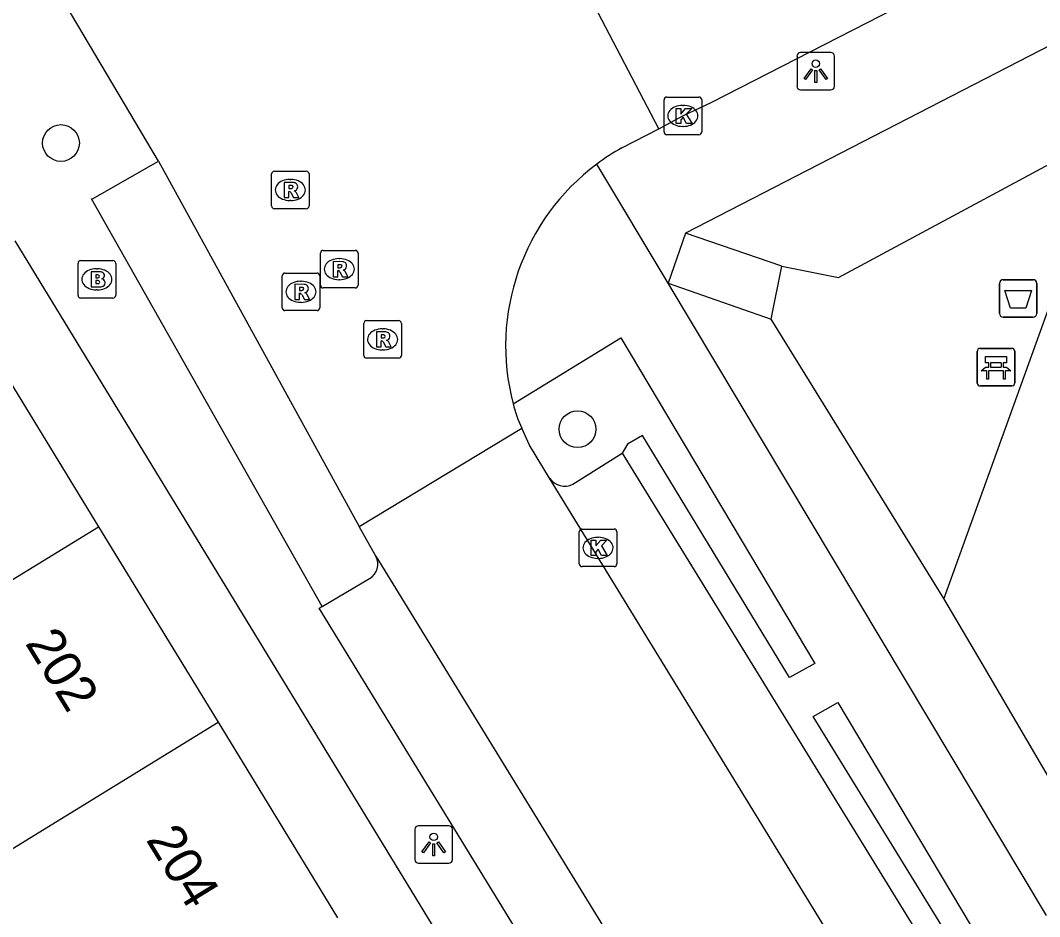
# Model space of a CAD drawing. Extents: x 159888 to 160757, y 384031 to 384746.
# Drawn here: x 160516.19 to 160543.3, y 384260.69 to 384284.54 of the extents above; entities that cross this region are included whole.
import ezdxf

# ---------------------------------------------------------------- set-up
doc = ezdxf.new("R2010")
doc.units = 0
for name, color, linetype in [('IMGEO_Afvalbak', 7, 'Continuous'), ('IMGEO_Bank', 7, 'Continuous'), ('IMGEO_Boom', 7, 'Continuous'), ('IMGEO_Brandkraan', 7, 'Continuous'), ('IMGEO_Groenvoorziening', 7, 'Continuous'), ('IMGEO_Kolk', 7, 'Continuous'), ('IMGEO_Lichtpunt', 7, 'Continuous'), ('IMGEO_Pand', 7, 'Continuous'), ('IMGEO_Pand_nummerreeks', 7, 'Continuous'), ('IMGEO_Parkeervlak_open', 7, 'Continuous'), ('IMGEO_Rijbaan_lokaal_open', 7, 'Continuous'), ('IMGEO_Rioolput', 7, 'Continuous'), ('IMGEO_Voetpad_open', 7, 'Continuous')]:
    doc.layers.add(name, color=color, linetype=linetype)

msp = doc.modelspace()

# ---------------------------------------------------------------- linework, layer by layer
at = {"layer": 'IMGEO_Afvalbak'}
for p, q in [((160542.23, 384276.738), (160542.23, 384277.538)), ((160542.23, 384277.538), (160542.23, 384276.738)), ((160542.33, 384277.638), (160543.12, 384277.638)), ((160543.12, 384277.638), (160542.33, 384277.638)), ((160543.22, 384277.538), (160543.22, 384276.738)), ((160543.22, 384276.738), (160543.22, 384277.538)), ((160543.12, 384276.638), (160542.33, 384276.638)), ((160542.33, 384276.638), (160543.12, 384276.638))]:
    msp.add_line(p, q, dxfattribs=at)
msp.add_lwpolyline([(160542.373, 384277.352), (160543.077, 384277.352), (160542.928, 384276.882), (160542.522, 384276.882), (160542.373, 384277.352)], dxfattribs=at)
for centre, start, end in [((160542.33, 384277.538), 90, 180), ((160542.33, 384277.538), 90, 180), ((160543.12, 384277.538), 0, 90), ((160543.12, 384277.538), 360, 90), ((160542.33, 384276.738), 180, 270), ((160542.33, 384276.738), 180, 270), ((160543.12, 384276.738), 270, 0), ((160543.12, 384276.738), 270, 0)]:
    msp.add_arc(centre, 0.1, start, end, dxfattribs=at)
at = {"layer": 'IMGEO_Bank'}
for p, q in [((160541.636, 384274.886), (160541.636, 384275.727)), ((160541.636, 384275.727), (160541.636, 384274.886)), ((160541.711, 384275.811), (160542.552, 384275.811)), ((160542.552, 384275.811), (160541.711, 384275.811)), ((160542.636, 384275.736), (160542.636, 384274.895)), ((160542.636, 384274.895), (160542.636, 384275.736)), ((160541.945, 384275.317), (160541.945, 384275.423)), ((160541.989, 384275.423), (160541.989, 384275.317)), ((160542.277, 384275.429), (160541.995, 384275.429)), ((160542.283, 384275.317), (160542.283, 384275.423)), ((160542.327, 384275.423), (160542.327, 384275.317)), ((160542.333, 384275.209), (160541.94, 384275.209)), ((160541.995, 384275.311), (160542.277, 384275.311)), ((160542.561, 384274.811), (160541.72, 384274.811)), ((160541.72, 384274.811), (160542.561, 384274.811))]:
    msp.add_line(p, q, dxfattribs=at)
for points in [[(160541.939, 384275.429), (160541.853, 384275.429), (160541.853, 384275.59), (160542.416, 384275.59), (160542.416, 384275.429), (160542.333, 384275.429)], [(160541.883, 384275.209), (160541.741, 384275.209), (160541.853, 384275.311), (160541.939, 384275.311)], [(160541.933, 384275.202), (160541.933, 384274.995), (160541.89, 384274.995), (160541.89, 384275.202)], [(160542.333, 384275.311), (160542.416, 384275.311), (160542.528, 384275.209), (160542.389, 384275.209)], [(160542.383, 384275.202), (160542.383, 384274.995), (160542.339, 384274.995), (160542.339, 384275.202)]]:
    msp.add_lwpolyline(points, dxfattribs=at)
for centre, radius, start, end in [((160541.714, 384275.733), 0.0779, 92.4484, 184.2845), ((160541.714, 384275.733), 0.0779, 92.4484, 184.2845), ((160542.558, 384275.733), 0.0779, 2.4484, 94.2845), ((160542.558, 384275.733), 0.0779, 2.4484, 94.2845), ((160541.938, 384275.422), 0.00671, 2.8957, 87.1043), ((160541.995, 384275.422), 0.00671, 92.8957, 177.1043), ((160542.277, 384275.422), 0.00671, 2.8957, 87.1043), ((160542.334, 384275.422), 0.00671, 92.8957, 177.1043), ((160541.883, 384275.202), 0.00671, 2.8957, 87.1043), ((160541.94, 384275.202), 0.00671, 92.8957, 177.1043), ((160541.938, 384275.318), 0.00671, 272.8957, 357.1043), ((160541.995, 384275.318), 0.00671, 182.8957, 267.1043), ((160542.277, 384275.318), 0.00671, 272.8957, 357.1043), ((160542.334, 384275.318), 0.00671, 182.8957, 267.1043), ((160542.332, 384275.202), 0.00671, 2.8957, 87.1043), ((160542.389, 384275.202), 0.00671, 92.8957, 177.1043), ((160541.714, 384274.889), 0.0779, 182.4484, 274.2845), ((160541.714, 384274.889), 0.0779, 182.4484, 274.2845), ((160542.558, 384274.889), 0.0779, 272.4484, 4.2845), ((160542.558, 384274.889), 0.0779, 272.4484, 4.2845)]:
    msp.add_arc(centre, radius, start, end, dxfattribs=at)
at = {"layer": 'IMGEO_Boom'}
for centre in [(160517.266, 384281.275), (160531.005, 384273.658)]:
    msp.add_circle(centre, 0.489, dxfattribs=at)
at = {"layer": 'IMGEO_Brandkraan'}
for p, q in [((160517.796, 384278.147), (160518.648, 384278.147)), ((160517.721, 384277.221), (160517.721, 384278.073)), ((160518.209, 384277.927), (160518.234, 384277.927)), ((160518.722, 384278.073), (160518.722, 384277.221)), ((160518.232, 384277.367), (160518.207, 384277.367)), ((160518.648, 384277.147), (160517.796, 384277.147))]:
    msp.add_line(p, q, dxfattribs=at)
for points in [[(160517.796, 384278.147), (160518.648, 384278.147)], [(160517.721, 384277.221), (160517.721, 384278.073)], [(160518.069, 384277.847), (160518.069, 384277.447), (160518.282, 384277.447)], [(160518.3, 384277.847), (160518.069, 384277.847)], [(160518.722, 384278.073), (160518.722, 384277.221)], [(160518.248, 384277.766), (160518.194, 384277.766), (160518.194, 384277.69)], [(160518.194, 384277.69), (160518.247, 384277.69)], [(160518.256, 384277.614), (160518.194, 384277.614), (160518.194, 384277.533)], [(160518.194, 384277.533), (160518.256, 384277.533)], [(160518.648, 384277.147), (160517.796, 384277.147)]]:
    msp.add_lwpolyline(points, dxfattribs=at)
for centre, radius, start, end in [((160517.798, 384278.071), 0.0765, 91.552, 178.448), ((160517.798, 384278.071), 0.0765, 91.552, 178.448), ((160518.646, 384278.071), 0.0765, 1.552, 88.448), ((160518.646, 384278.071), 0.0765, 1.552, 88.448), ((160518.304, 384277.702), 0.145, 59.4692, 91.5367), ((160518.329, 384277.749), 0.0922, 285.5137, 58.1501), ((160518.249, 384277.728), 0.0379, 267.8285, 90.9355), ((160518.257, 384277.573), 0.0404, 269.8759, 90.5077), ((160518.334, 384277.557), 0.105, 301.3115, 78.989), ((160518.288, 384277.698), 0.251, 268.6676, 293.5347), ((160517.798, 384277.223), 0.0765, 181.552, 268.448), ((160517.798, 384277.223), 0.0765, 181.552, 268.448), ((160518.646, 384277.223), 0.0765, 271.552, 358.448), ((160518.646, 384277.223), 0.0765, 271.552, 358.448)]:
    msp.add_arc(centre, radius, start, end, dxfattribs=at)
for centre, major_axis, ratio, start_param, end_param in [((160518.208, 384277.647), (-0.387, 0.002), 0.722429, 4.712389, 7.853982), ((160518.233, 384277.647), (-0.39, 0.002), 0.717154, 1.570796, 4.712389)]:
    msp.add_ellipse(centre, major_axis=major_axis, ratio=ratio, start_param=start_param, end_param=end_param, dxfattribs=at)
at = {"layer": 'IMGEO_Groenvoorziening'}
for points in [[(160536.442, 384278.002), (160537.944, 384277.697), (160549.322, 384283.817), (160551.212, 384280.795), (160550.654, 384280.266), (160550.225, 384279.629), (160550.169, 384278.862), (160550.319, 384278.053), (160551.037, 384276.806)], [(160551.037, 384276.806), (160544.321, 384279.062), (160540.748, 384269.155)], [(160540.748, 384269.155), (160536.155, 384276.583)], [(160543.871, 384263.833), (160541.766, 384267.42), (160540.748, 384269.155)]]:
    msp.add_lwpolyline(points, dxfattribs=at)
at = {"layer": 'IMGEO_Kolk'}
for p, q in [((160533.307, 384281.571), (160533.307, 384282.423)), ((160533.382, 384282.497), (160534.234, 384282.497)), ((160534.308, 384282.423), (160534.308, 384281.571)), ((160533.795, 384282.277), (160533.82, 384282.277)), ((160533.818, 384281.717), (160533.793, 384281.717)), ((160534.234, 384281.497), (160533.382, 384281.497)), ((160531.05, 384270.076), (160531.05, 384270.928)), ((160531.125, 384271.002), (160531.977, 384271.002)), ((160531.538, 384270.782), (160531.563, 384270.782)), ((160532.051, 384270.928), (160532.051, 384270.076)), ((160531.561, 384270.222), (160531.536, 384270.222)), ((160531.977, 384270.002), (160531.125, 384270.002))]:
    msp.add_line(p, q, dxfattribs=at)
for points in [[(160533.307, 384281.571), (160533.307, 384282.423)], [(160533.382, 384282.497), (160534.234, 384282.497)], [(160534.308, 384282.423), (160534.308, 384281.571)], [(160533.628, 384282.197), (160533.751, 384282.197), (160533.751, 384282.046), (160533.881, 384282.197), (160534.045, 384282.197), (160533.899, 384282.046), (160534.052, 384281.797), (160533.9, 384281.797), (160533.815, 384281.961), (160533.751, 384281.894), (160533.751, 384281.797), (160533.628, 384281.797), (160533.628, 384282.197)], [(160534.234, 384281.497), (160533.382, 384281.497)], [(160531.05, 384270.076), (160531.05, 384270.928)], [(160531.125, 384271.002), (160531.977, 384271.002)], [(160532.051, 384270.928), (160532.051, 384270.076)], [(160531.371, 384270.702), (160531.494, 384270.702), (160531.494, 384270.551), (160531.624, 384270.702), (160531.788, 384270.702), (160531.642, 384270.551), (160531.795, 384270.302), (160531.643, 384270.302), (160531.558, 384270.466), (160531.494, 384270.399), (160531.494, 384270.302), (160531.371, 384270.302), (160531.371, 384270.702)], [(160531.977, 384270.002), (160531.125, 384270.002)]]:
    msp.add_lwpolyline(points, dxfattribs=at)
for centre, start, end in [((160533.384, 384282.421), 91.552, 178.448), ((160533.384, 384282.421), 91.552, 178.448), ((160534.232, 384282.421), 1.552, 88.448), ((160534.232, 384282.421), 1.552, 88.448), ((160533.384, 384281.573), 181.552, 268.448), ((160533.384, 384281.573), 181.552, 268.448), ((160534.232, 384281.573), 271.552, 358.448), ((160534.232, 384281.573), 271.552, 358.448), ((160531.127, 384270.926), 91.552, 178.448), ((160531.127, 384270.926), 91.552, 178.448), ((160531.975, 384270.926), 1.552, 88.448), ((160531.975, 384270.926), 1.552, 88.448), ((160531.127, 384270.078), 181.552, 268.448), ((160531.127, 384270.078), 181.552, 268.448), ((160531.975, 384270.078), 271.552, 358.448), ((160531.975, 384270.078), 271.552, 358.448)]:
    msp.add_arc(centre, 0.0765, start, end, dxfattribs=at)
for centre, major_axis, ratio, start_param, end_param in [((160533.794, 384281.997), (-0.387, 0.002), 0.722429, 4.712389, 7.853982), ((160533.819, 384281.997), (-0.39, 0.002), 0.717154, 1.570796, 4.712389), ((160531.537, 384270.502), (-0.387, 0.002), 0.722429, 4.712389, 7.853982), ((160531.562, 384270.502), (-0.39, 0.002), 0.717154, 1.570796, 4.712389)]:
    msp.add_ellipse(centre, major_axis=major_axis, ratio=ratio, start_param=start_param, end_param=end_param, dxfattribs=at)
at = {"layer": 'IMGEO_Lichtpunt'}
for p, q in [((160536.843, 384283.589), (160536.843, 384282.782)), ((160536.843, 384283.589), (160536.843, 384282.782)), ((160537.745, 384283.684), (160536.937, 384283.684)), ((160537.745, 384283.684), (160536.937, 384283.684)), ((160537.839, 384282.782), (160537.839, 384283.589)), ((160537.839, 384282.782), (160537.839, 384283.589)), ((160536.937, 384282.688), (160537.745, 384282.688)), ((160536.937, 384282.688), (160537.745, 384282.688)), ((160526.681, 384263.012), (160526.681, 384262.205)), ((160526.681, 384263.012), (160526.681, 384262.205)), ((160527.583, 384263.107), (160526.775, 384263.107)), ((160527.583, 384263.107), (160526.775, 384263.107)), ((160527.677, 384262.205), (160527.677, 384263.012)), ((160527.677, 384262.205), (160527.677, 384263.012)), ((160526.775, 384262.111), (160527.583, 384262.111)), ((160526.775, 384262.111), (160527.583, 384262.111))]:
    msp.add_line(p, q, dxfattribs=at)
for points in [[(160537.217, 384283.253), (160537.256, 384283.225), (160537.068, 384282.963), (160537.03, 384282.99), (160537.217, 384283.253)], [(160537.429, 384283.225), (160537.467, 384283.252), (160537.654, 384282.99), (160537.615, 384282.962), (160537.429, 384283.225)], [(160537.319, 384283.205), (160537.366, 384283.205), (160537.366, 384282.883), (160537.319, 384282.883), (160537.319, 384283.205)], [(160527.055, 384262.676), (160527.094, 384262.648), (160526.906, 384262.386), (160526.868, 384262.413), (160527.055, 384262.676)], [(160527.157, 384262.628), (160527.204, 384262.628), (160527.204, 384262.306), (160527.157, 384262.306), (160527.157, 384262.628)], [(160527.267, 384262.648), (160527.305, 384262.675), (160527.492, 384262.413), (160527.453, 384262.385), (160527.267, 384262.648)]]:
    msp.add_lwpolyline(points, dxfattribs=at)
for centre in [(160537.342, 384283.387), (160527.18, 384262.81)]:
    msp.add_circle(centre, 0.0994, dxfattribs=at)
for centre, start, end in [((160536.937, 384283.589), 90, 180), ((160536.937, 384283.589), 90, 180), ((160537.745, 384283.589), 0, 90), ((160537.745, 384283.589), 0, 90), ((160536.937, 384282.782), 180, 270), ((160536.937, 384282.782), 180, 270), ((160537.745, 384282.782), 270, 0), ((160537.745, 384282.782), 270, 360), ((160526.775, 384263.012), 90, 180), ((160526.775, 384263.012), 90, 180), ((160527.583, 384263.012), 0, 90), ((160527.583, 384263.012), 0, 90), ((160526.775, 384262.205), 180, 270), ((160526.775, 384262.205), 180, 270), ((160527.583, 384262.205), 270, 0), ((160527.583, 384262.205), 270, 360)]:
    msp.add_arc(centre, 0.0946, start, end, dxfattribs=at)
at = {"layer": 'IMGEO_Pand'}
for points in [[(160511.406, 384266.852), (160508.164, 384272.127), (160515.039, 384276.335), (160518.261, 384271.065)], [(160511.406, 384266.852), (160518.261, 384271.065)], [(160518.261, 384271.065), (160521.443, 384265.86)], [(160511.115, 384259.493), (160514.645, 384261.683), (160521.443, 384265.86)], [(160521.443, 384265.86), (160524.625, 384260.656)]]:
    msp.add_lwpolyline(points, dxfattribs=at)
at = {"layer": 'IMGEO_Parkeervlak_open'}
for points in [[(160530.88, 384272.193), (160532.196, 384273.02)], [(160524.213, 384268.938), (160525.476, 384269.683)]]:
    msp.add_lwpolyline(points, dxfattribs=at)
for centre, radius, start, end in [((160530.667, 384272.638), 0.494, 215.1581, 295.5926), ((160525.247, 384270.064), 0.445, 300.9358, 28.554)]:
    msp.add_arc(centre, radius, start, end, dxfattribs=at)
at = {"layer": 'IMGEO_Rijbaan_lokaal_open'}
for points in [[(160533.164, 384281.656), (160533.808, 384281.997), (160534.575, 384282.359), (160579.578, 384305.42)], [(160533.164, 384281.656), (160530.447, 384286.864)], [(160519.864, 384280.79), (160516.788, 384285.989)], [(160532.184, 384281.146), (160533.164, 384281.656)], [(160519.864, 384280.79), (160525.198, 384271.067)], [(160525.198, 384271.067), (160529.522, 384273.687)], [(160530.263, 384272.354), (160529.728, 384273.233), (160529.522, 384273.687)], [(160545.852, 384246.914), (160538, 384259.726), (160530.263, 384272.354)], [(160525.638, 384270.277), (160525.198, 384271.067)], [(160525.638, 384270.277), (160538.092, 384250)]]:
    msp.add_lwpolyline(points, dxfattribs=at)
for centre, radius, start, end in [((160535.135, 384275.867), 6.048, 119.2067, 126.7321), ((160535.129, 384275.877), 6.036, 126.747, 194.7842), ((160532.652, 384275.155), 3.457, 193.6867, 205.1288)]:
    msp.add_arc(centre, radius, start, end, dxfattribs=at)
at = {"layer": 'IMGEO_Rioolput'}
for p, q in [((160522.94, 384280.525), (160523.792, 384280.525)), ((160522.865, 384279.599), (160522.865, 384280.451)), ((160523.353, 384280.305), (160523.378, 384280.305)), ((160523.866, 384280.451), (160523.866, 384279.599)), ((160523.376, 384279.745), (160523.351, 384279.745)), ((160523.792, 384279.525), (160522.94, 384279.525)), ((160524.243, 384278.418), (160525.095, 384278.418)), ((160524.168, 384277.492), (160524.168, 384278.344)), ((160524.656, 384278.198), (160524.681, 384278.198)), ((160525.169, 384278.344), (160525.169, 384277.492)), ((160523.224, 384277.815), (160524.076, 384277.815)), ((160523.149, 384276.889), (160523.149, 384277.741)), ((160523.637, 384277.595), (160523.662, 384277.595)), ((160524.15, 384277.741), (160524.15, 384276.889)), ((160524.679, 384277.638), (160524.654, 384277.638)), ((160525.095, 384277.418), (160524.243, 384277.418)), ((160523.66, 384277.035), (160523.635, 384277.035)), ((160524.076, 384276.815), (160523.224, 384276.815)), ((160525.32, 384275.623), (160525.32, 384276.475)), ((160525.395, 384276.549), (160526.247, 384276.549)), ((160526.321, 384276.475), (160526.321, 384275.623)), ((160525.808, 384276.329), (160525.833, 384276.329)), ((160525.831, 384275.769), (160525.806, 384275.769)), ((160526.247, 384275.549), (160525.395, 384275.549))]:
    msp.add_line(p, q, dxfattribs=at)
for points in [[(160522.94, 384280.525), (160523.792, 384280.525)], [(160522.865, 384279.599), (160522.865, 384280.451)], [(160523.866, 384280.451), (160523.866, 384279.599)], [(160523.454, 384280.223), (160523.202, 384280.225), (160523.202, 384279.825)], [(160523.202, 384279.825), (160523.326, 384279.825), (160523.326, 384279.987), (160523.337, 384279.987)], [(160523.38, 384280.144), (160523.326, 384280.144), (160523.326, 384280.063)], [(160523.326, 384280.063), (160523.378, 384280.063)], [(160523.384, 384279.958), (160523.455, 384279.825), (160523.595, 384279.825), (160523.53, 384279.951)], [(160523.792, 384279.525), (160522.94, 384279.525)], [(160524.243, 384278.418), (160525.095, 384278.418)], [(160524.168, 384277.492), (160524.168, 384278.344)], [(160524.757, 384278.116), (160524.505, 384278.118), (160524.505, 384277.718)], [(160525.169, 384278.344), (160525.169, 384277.492)], [(160523.224, 384277.815), (160524.076, 384277.815)], [(160524.505, 384277.718), (160524.629, 384277.718), (160524.629, 384277.88), (160524.64, 384277.88)], [(160524.683, 384278.037), (160524.629, 384278.037), (160524.629, 384277.956)], [(160524.629, 384277.956), (160524.681, 384277.956)], [(160524.687, 384277.851), (160524.758, 384277.718), (160524.898, 384277.718), (160524.833, 384277.844)], [(160523.149, 384276.889), (160523.149, 384277.741)], [(160524.15, 384277.741), (160524.15, 384276.889)], [(160523.738, 384277.513), (160523.486, 384277.515), (160523.486, 384277.115)], [(160523.486, 384277.115), (160523.61, 384277.115), (160523.61, 384277.277), (160523.621, 384277.277)], [(160523.664, 384277.434), (160523.61, 384277.434), (160523.61, 384277.353)], [(160523.61, 384277.353), (160523.662, 384277.353)], [(160525.095, 384277.418), (160524.243, 384277.418)], [(160523.668, 384277.248), (160523.739, 384277.115), (160523.879, 384277.115), (160523.814, 384277.241)], [(160524.076, 384276.815), (160523.224, 384276.815)], [(160525.32, 384275.623), (160525.32, 384276.475)], [(160525.395, 384276.549), (160526.247, 384276.549)], [(160526.321, 384276.475), (160526.321, 384275.623)], [(160525.909, 384276.247), (160525.657, 384276.249), (160525.657, 384275.849)], [(160525.657, 384275.849), (160525.781, 384275.849), (160525.781, 384276.011), (160525.792, 384276.011)], [(160525.835, 384276.168), (160525.781, 384276.168), (160525.781, 384276.087)], [(160525.781, 384276.087), (160525.833, 384276.087)], [(160525.839, 384275.982), (160525.91, 384275.849), (160526.05, 384275.849), (160525.985, 384275.975)], [(160526.247, 384275.549), (160525.395, 384275.549)]]:
    msp.add_lwpolyline(points, dxfattribs=at)
for centre, radius, start, end in [((160522.942, 384280.449), 0.0765, 91.552, 178.448), ((160522.942, 384280.449), 0.0765, 91.552, 178.448), ((160523.79, 384280.449), 0.0765, 1.552, 88.448), ((160523.79, 384280.449), 0.0765, 1.552, 88.448), ((160523.336, 384279.934), 0.0533, 26.0293, 88.6989), ((160523.362, 384280.252), 0.19, 274.7715, 282.9687), ((160523.386, 384280.048), 0.0964, 77.0061, 93.1865), ((160523.4, 384280.105), 0.0378, 276.6634, 79.6772), ((160523.453, 384280.113), 0.109, 350.3612, 89.416), ((160523.451, 384280.113), 0.112, 277.5842, 350.9817), ((160523.435, 384279.898), 0.108, 29.5134, 73.7905), ((160522.942, 384279.601), 0.0765, 181.552, 268.448), ((160522.942, 384279.601), 0.0765, 181.552, 268.448), ((160523.79, 384279.601), 0.0765, 271.552, 358.448), ((160523.79, 384279.601), 0.0765, 271.552, 358.448), ((160524.245, 384278.342), 0.0765, 91.552, 178.448), ((160524.245, 384278.342), 0.0765, 91.552, 178.448), ((160525.093, 384278.342), 0.0765, 1.552, 88.448), ((160525.093, 384278.342), 0.0765, 1.552, 88.448), ((160524.756, 384278.006), 0.109, 350.3612, 89.416), ((160523.226, 384277.739), 0.0765, 91.552, 178.448), ((160523.226, 384277.739), 0.0765, 91.552, 178.448), ((160524.074, 384277.739), 0.0765, 1.552, 88.448), ((160524.074, 384277.739), 0.0765, 1.552, 88.448), ((160524.639, 384277.827), 0.0533, 26.0293, 88.6989), ((160524.665, 384278.145), 0.19, 274.7715, 282.9687), ((160524.689, 384277.941), 0.0964, 77.0061, 93.1865), ((160524.703, 384277.998), 0.0378, 276.6634, 79.6772), ((160524.754, 384278.006), 0.112, 277.5842, 350.9817), ((160524.738, 384277.791), 0.108, 29.5134, 73.7905), ((160523.62, 384277.224), 0.0533, 26.0293, 88.6989), ((160523.646, 384277.542), 0.19, 274.7715, 282.9687), ((160523.67, 384277.338), 0.0964, 77.0061, 93.1865), ((160523.684, 384277.395), 0.0378, 276.6634, 79.6772), ((160523.737, 384277.403), 0.109, 350.3612, 89.416), ((160523.735, 384277.403), 0.112, 277.5842, 350.9817), ((160523.719, 384277.188), 0.108, 29.5134, 73.7905), ((160524.245, 384277.494), 0.0765, 181.552, 268.448), ((160524.245, 384277.494), 0.0765, 181.552, 268.448), ((160525.093, 384277.494), 0.0765, 271.552, 358.448), ((160525.093, 384277.494), 0.0765, 271.552, 358.448), ((160523.226, 384276.891), 0.0765, 181.552, 268.448), ((160523.226, 384276.891), 0.0765, 181.552, 268.448), ((160524.074, 384276.891), 0.0765, 271.552, 358.448), ((160524.074, 384276.891), 0.0765, 271.552, 358.448), ((160525.397, 384276.473), 0.0765, 91.552, 178.448), ((160525.397, 384276.473), 0.0765, 91.552, 178.448), ((160526.245, 384276.473), 0.0765, 1.552, 88.448), ((160526.245, 384276.473), 0.0765, 1.552, 88.448), ((160525.908, 384276.137), 0.109, 350.3612, 89.416), ((160525.791, 384275.958), 0.0533, 26.0293, 88.6989), ((160525.817, 384276.276), 0.19, 274.7715, 282.9687), ((160525.841, 384276.072), 0.0964, 77.0061, 93.1865), ((160525.855, 384276.129), 0.0378, 276.6634, 79.6772), ((160525.906, 384276.137), 0.112, 277.5842, 350.9817), ((160525.89, 384275.922), 0.108, 29.5134, 73.7905), ((160525.397, 384275.625), 0.0765, 181.552, 268.448), ((160525.397, 384275.625), 0.0765, 181.552, 268.448), ((160526.245, 384275.625), 0.0765, 271.552, 358.448), ((160526.245, 384275.625), 0.0765, 271.552, 358.448)]:
    msp.add_arc(centre, radius, start, end, dxfattribs=at)
for centre, major_axis, ratio, start_param, end_param in [((160523.352, 384280.025), (-0.387, 0.002), 0.722429, 4.712389, 7.853982), ((160523.377, 384280.025), (-0.39, 0.002), 0.717154, 1.570796, 4.712389), ((160524.655, 384277.918), (-0.387, 0.002), 0.722429, 4.712389, 7.853982), ((160524.68, 384277.918), (-0.39, 0.002), 0.717154, 1.570796, 4.712389), ((160523.636, 384277.315), (-0.387, 0.002), 0.722429, 4.712389, 7.853982), ((160523.661, 384277.315), (-0.39, 0.002), 0.717154, 1.570796, 4.712389), ((160525.807, 384276.049), (-0.387, 0.002), 0.722429, 4.712389, 7.853982), ((160525.832, 384276.049), (-0.39, 0.002), 0.717154, 1.570796, 4.712389)]:
    msp.add_ellipse(centre, major_axis=major_axis, ratio=ratio, start_param=start_param, end_param=end_param, dxfattribs=at)
at = {"layer": 'IMGEO_Voetpad_open'}
for points in [[(160551.279, 384287.856), (160533.88, 384278.879)], [(160524.213, 384268.938), (160518.08, 384279.791), (160518.101, 384279.79), (160519.864, 384280.79)], [(160533.414, 384277.545), (160531.518, 384280.714)], [(160516.041, 384278.668), (160533.512, 384250), (160556.908, 384211.788), (160559.072, 384207.22), (160560.667, 384202.459), (160562.778, 384192.752), (160563.394, 384187.766), (160564.326, 384177.793)], [(160533.88, 384278.879), (160533.414, 384277.545)], [(160536.442, 384278.002), (160533.88, 384278.879)], [(160536.155, 384276.583), (160536.442, 384278.002)], [(160543.477, 384260.72), (160533.414, 384277.545)], [(160533.414, 384277.545), (160536.155, 384276.583)], [(160529.293, 384274.337), (160532.159, 384276.087), (160537.318, 384267.427), (160536.639, 384267.05), (160532.731, 384273.49), (160532.335, 384273.257), (160532.196, 384273.02)], [(160532.196, 384273.02), (160539.733, 384260.755), (160547.34, 384248.378), (160546.057, 384247.544)], [(160536.235, 384249.14), (160524.133, 384268.893), (160524.213, 384268.938)], [(160541.457, 384259.202), (160537.269, 384266.016), (160537.932, 384266.383), (160542.027, 384259.51), (160541.457, 384259.202)]]:
    msp.add_lwpolyline(points, dxfattribs=at)

# ---------------------------------------------------------------- texts
at = {"layer": 'IMGEO_Pand_nummerreeks'}
for s, p in [('202', (160516.297, 384267.966)), ('204', (160519.511, 384262.735))]:
    msp.add_text(s, height=1, rotation=301.564, dxfattribs=at).set_placement(p)

doc.saveas('drawing.dxf')
